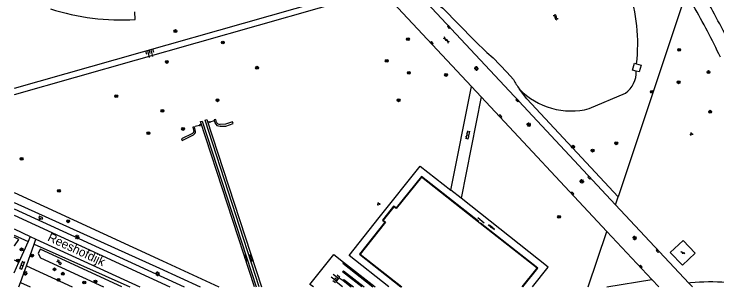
# Model space of a CAD drawing. Extents: x 128000 to 131008, y 398996 to 402500.
# Drawn here: x 128000 to 128199.6, y 399000 to 399077.6 of the extents above; entities that cross this region are included whole.
import ezdxf

# ---------------------------------------------------------------- set-up
doc = ezdxf.new("R2010")
doc.units = 0
for name, color, linetype in [('gg-afsc-hekwerk', 7, 'Continuous'), ('gg-afsc-muur', 7, 'Continuous'), ('gg-anno-openbare ruimte label', 7, 'Continuous'), ('gg-knt-BGT kruinlijn', 7, 'Continuous'), ('gg-knt-bovenkant onderkant talud', 7, 'Continuous'), ('gg-knt-verharding', 7, 'Continuous'), ('gg-knt-verharding nz', 7, 'Continuous'), ('gg-kntw-bovenkant insteek waterloop', 7, 'Continuous'), ('gg-kntw-greppel-droge sloot', 7, 'Continuous'), ('gg-kwrk-betonelement', 7, 'Continuous'), ('gt-grn-groengrens', 7, 'Continuous'), ('gt-symb-boom', 7, 'Continuous'), ('gt-symb-camera', 7, 'Continuous'), ('gt-symb-gesloten verharding', 7, 'Continuous'), ('gt-symb-groenvak', 7, 'Continuous'), ('gt-symb-klinker verharding', 7, 'Continuous'), ('gt-symb-kolk', 7, 'Continuous'), ('gt-symb-lichtmast', 7, 'Continuous'), ('gt-symb-speelvoorziening', 7, 'Continuous'), ('gt-symb-talud symbool', 7, 'Continuous'), ('gt-symb-tegel verharding', 7, 'Continuous'), ('gt-symb-watersymbool', 7, 'Continuous')]:
    doc.layers.add(name, color=color, linetype=linetype)

# ---------------------------------------------------------------- blocks, each defined once
blk = doc.blocks.new('gt0-KOLK')
at = {"layer": 'gt-symb-kolk'}
blk.add_lwpolyline([(0, 0), (0.38, 0), (0.38, 0.4), (-0.38, 0.4), (-0.38, 0), (0, 0)], dxfattribs=at)
blk = doc.blocks.new('gt0-WA')
at = {"layer": 'gt-symb-watersymbool'}
for centre, start, end in [((-0.32, 0.02), 28.0725, 151.9275), ((0.43, 0.42), 208.0725, 331.9275), ((-0.32, -0.43), 28.0725, 151.9275), ((0.43, -0.03), 208.0725, 331.9275)]:
    blk.add_arc(centre, 0.425, start, end, dxfattribs=at)
blk = doc.blocks.new('gt0-BOOM')
at = {"layer": 'gt-symb-boom'}
for radius in [0.4, 0.2]:
    blk.add_circle((0, 0), radius, dxfattribs=at)
blk = doc.blocks.new('gt0-TALUD_1')
at = {"layer": 'gt-symb-talud symbool'}
for p, q in [((-1, -1), (-1, 0)), ((-0.5, -2), (-0.5, 0)), ((0.5, -2), (0.5, 0)), ((1, -1), (1, 0)), ((0, -1), (0, 0))]:
    blk.add_line(p, q, dxfattribs=at)
blk = doc.blocks.new('gt0-GRVAK')
at = {"layer": 'gt-symb-groenvak'}
for p, q in [((-0.11, 0.19), (-0.23, 0.24)), ((-0.18, 0.15), (0.09, 0.15)), ((-0.09, 0.21), (-0.16, 0.32)), ((-0.05, 0.21), (-0.05, 0.39)), ((0, 0.21), (0.06, 0.32)), ((0.01, 0.19), (0.13, 0.24)), ((0.26, -0.05), (0.2, 0.06)), ((0.3, -0.05), (0.3, 0.13)), ((0.35, -0.05), (0.41, 0.06)), ((-0.25, -0.23), (-0.36, -0.18)), ((-0.32, -0.26), (-0.05, -0.26)), ((-0.23, -0.21), (-0.29, -0.1)), ((-0.18, -0.2), (-0.18, -0.02)), ((-0.14, -0.21), (-0.07, -0.1)), ((-0.12, -0.23), (0, -0.18)), ((0.24, -0.07), (0.12, -0.02)), ((0.17, -0.11), (0.44, -0.11)), ((0.37, -0.07), (0.49, -0.02))]:
    blk.add_line(p, q, dxfattribs=at)
blk = doc.blocks.new('gt0-GESVH1')
at = {"layer": 'gt-symb-gesloten verharding'}
for p, q in [((-0.99, -0.26), (0.01, 0.24)), ((0.01, -0.26), (-0.99, 0.24)), ((0.01, 0.24), (1.01, -0.26)), ((1.01, 0.24), (0.01, -0.26))]:
    blk.add_line(p, q, dxfattribs=at)
blk = doc.blocks.new('gt0-LMAST')
at = {"layer": 'gt-symb-lichtmast'}
for p, q in [((-0.18, 0.17), (-0.45, 0.44)), ((-0.01, 0.25), (-0.01, 0.62)), ((0.17, 0.17), (0.44, 0.44)), ((-0.26, 0), (-0.63, 0)), ((-0.18, -0.18), (-0.45, -0.45)), ((-0.01, -0.25), (-0.01, -0.63)), ((0.44, -0.45), (0.17, -0.18)), ((0.24, 0), (0.62, 0))]:
    blk.add_line(p, q, dxfattribs=at)
blk.add_circle((-0.01, 0), 0.25, dxfattribs=at)
blk = doc.blocks.new('gt0-KL1')
at = {"layer": 'gt-symb-klinker verharding'}
for p, q in [((-1.15, 0.3), (1.15, 0.3)), ((-1, -0.3), (-1, 0.3)), ((-0.5, 0.3), (-0.5, 0.45)), ((0, -0.3), (0, 0.3)), ((0.5, 0.3), (0.5, 0.45)), ((1, -0.3), (1, 0.3)), ((-1.15, -0.3), (1.15, -0.3)), ((-0.5, -0.45), (-0.5, -0.3)), ((0.5, -0.45), (0.5, -0.3))]:
    blk.add_line(p, q, dxfattribs=at)
blk = doc.blocks.new('gt0-CAMERA')
at = {"layer": 'gt-symb-camera'}
for points in [[(0.07, 0.48), (0.75, 0.16), (0.92, 0.51), (-0.12, 1), (-0.28, 0.65), (-0.07, 0.55)], [(0.07, 0.48), (0.07, 0), (-0.07, 0), (-0.07, 0.55)]]:
    blk.add_lwpolyline(points, dxfattribs=at)
blk = doc.blocks.new('gt0-SV')
at = {"layer": 'gt-symb-speelvoorziening'}
for p, q in [((-0.48, 0.26), (-0.08, 0.1)), ((0.54, -0.08), (-0.45, 0.32)), ((0.13, 0.01), (0.51, -0.14))]:
    blk.add_line(p, q, dxfattribs=at)
for centre, radius, start, end in [((-0.47, 0.29), 0.0369, 63.6251, 252.6602), ((0, -0.01), 0.128, 127.6866, 8.5986), ((0.53, -0.11), 0.0363, 243.5085, 72.5436)]:
    blk.add_arc(centre, radius, start, end, dxfattribs=at)
blk = doc.blocks.new('gt0-TEG1')
at = {"layer": 'gt-symb-tegel verharding'}
for p, q in [((-1.13, 0), (1.12, 0)), ((-0.9, -0.25), (-0.9, 0.25)), ((-0.45, -0.25), (-0.45, 0.25)), ((0, -0.25), (0, 0.25)), ((0.45, -0.25), (0.45, 0.25)), ((0.9, -0.25), (0.9, 0.25))]:
    blk.add_line(p, q, dxfattribs=at)

msp = doc.modelspace()

# ---------------------------------------------------------------- linework, layer by layer
at = {"layer": 'gg-afsc-hekwerk'}
for p, q in [((128052.69, 399045.93), (128051.41, 399045.6)), ((128056.86, 399047.27), (128055.62, 399046.86)), ((128133.55, 399018.17), (128131.69, 399019.64)), ((128098.12, 399009.3), (128109.88, 399000))]:
    msp.add_line(p, q, dxfattribs=at)
for points in [[(128131.96, 399018.59), (128115.72, 399031.43), (128108.51, 399022.49), (128107.81, 399023.01), (128104.61, 399018.97), (128105.32, 399018.41), (128098.12, 399009.3)], [(128144.54, 399000), (128148.77, 399005.33), (128132.48, 399018.17)]]:
    msp.add_lwpolyline(points, dxfattribs=at)
at = {"layer": 'gg-afsc-muur'}
msp.add_line((128052.69, 399045.93), (128052.7, 399045.86), dxfattribs=at)
for points in [[(128052.7, 399045.86), (128052.94, 399045.93), (128052.87, 399046.2), (128052.63, 399046.13), (128052.69, 399045.93)], [(128055.32, 399046.96), (128055.56, 399047.03), (128055.62, 399046.86)], [(128055.62, 399046.86), (128055.64, 399046.77), (128055.4, 399046.7), (128055.32, 399046.96)]]:
    msp.add_lwpolyline(points, dxfattribs=at)
at = {"layer": 'gg-knt-BGT kruinlijn'}
msp.add_lwpolyline([(128078.95, 399109.26), (128101.38, 399085.3), (128000, 399056.41)], dxfattribs=at)
at = {"layer": 'gg-knt-bovenkant onderkant talud'}
for points in [[(128079.75, 399110.39), (128104.01, 399084.31), (128000, 399054.57)], [(128085.06, 399000), (128084.03, 399000.71), (128090.83, 399009.27), (128093.61, 399007.09)], [(128093.25, 399000), (128091.49, 399001.41), (128092.38, 399002.62), (128093.47, 399001.8)]]:
    msp.add_lwpolyline(points, dxfattribs=at)
at = {"layer": 'gg-knt-verharding'}
for p, q in [((128007.41, 399188.33), (128129.97, 399056.96)), ((128124.09, 399027.49), (128129.97, 399056.96)), ((128129.97, 399056.96), (128132.7, 399054.04)), ((128132.7, 399054.04), (128126.99, 399025.2)), ((128132.7, 399054.04), (128168.35, 399015.81)), ((128126.99, 399025.2), (128124.09, 399027.49)), ((128000, 399022.24), (128048.27, 399000)), ((128191.69, 399001.04), (128170.85, 399023.39)), ((128000, 399016.49), (128004.6, 399014.36)), ((128004.6, 399014.36), (128003.98, 399012.95)), ((128004.6, 399014.36), (128006.2, 399013.62)), ((128168.35, 399015.81), (128181.16, 399002.09)), ((128003.98, 399012.95), (128001.35, 399007.05)), ((128003.51, 399006.05), (128005.69, 399012.18)), ((128005.69, 399012.18), (128006.2, 399013.62)), ((128006.2, 399013.62), (128035.69, 399000)), ((128000, 399003.99), (128001.35, 399007.05)), ((128001.81, 399001.28), (128003.51, 399006.05)), ((128093.61, 399007.09), (128102.58, 399000)), ((128168.4, 399000), (128181.16, 399002.09)), ((128181.16, 399002.09), (128183.1, 399000)), ((128001.35, 399000), (128001.81, 399001.28)), ((128001.81, 399001.28), (128004.58, 399000)), ((128093.47, 399001.8), (128095.74, 399000)), ((128191.69, 399001.04), (128192.66, 399000))]:
    msp.add_line(p, q, dxfattribs=at)
for points in [[(128170.85, 399023.39), (128142.05, 399054.28), (128080.14, 399120.59)], [(128068.25, 399000), (128052.95, 399047.03), (128053.39, 399047.17), (128068.77, 399000)], [(128069.64, 399000), (128054.31, 399047.43), (128054.76, 399047.58), (128070.26, 399000)], [(128106.49, 399000), (128095.17, 399008.96), (128103.67, 399019.71), (128115.39, 399034.37), (128124.09, 399027.49)], [(128144.35, 399000), (128148.56, 399005.3), (128132.39, 399018.05), (128115.74, 399031.22), (128108.53, 399022.28), (128107.84, 399022.8), (128104.82, 399018.99), (128105.53, 399018.43), (128098.33, 399009.33), (128110.12, 399000)], [(128147.23, 399000), (128151.72, 399005.67), (128126.99, 399025.2)], [(128189.82, 399006.15), (128193.46, 399009.58), (128190.02, 399013.22), (128186.38, 399009.8), (128189.82, 399006.15)], [(128093.61, 399007.09), (128093.36, 399006.78), (128101.93, 399000)], [(128098.76, 399000), (128093.33, 399004.3), (128093.58, 399004.61), (128099.41, 399000)], [(128093.47, 399001.8), (128093.71, 399002.12), (128096.38, 399000)]]:
    msp.add_lwpolyline(points, dxfattribs=at)
for centre, radius, start, end in [((128007.68, 398974.12), 217.44, 25.4027, 29.7543), ((127991.92, 398965.34), 231.42, 25.5931, 29.6798)]:
    msp.add_arc(centre, radius, start, end, dxfattribs=at)
at = {"layer": 'gg-knt-verharding nz'}
msp.add_line((128000, 399020.4), (128044.27, 399000), dxfattribs=at)
at = {"layer": 'gg-kntw-bovenkant insteek waterloop'}
msp.add_line((128163.36, 399050.69), (128173.64, 399055.07), dxfattribs=at)
for points in [[(128081.22, 399126.21), (128081.55, 399125.38), (128082.38, 399120.6), (128084.89, 399118.4), (128085.76, 399116.26), (128088.47, 399112.9), (128090.5, 399112.72), (128097.76, 399105.12), (128101.76, 399099.2), (128118.49, 399081.76), (128121.81, 399079.22), (128130.8, 399070.07), (128134.26, 399066.61), (128136.07, 399065.1), (128140, 399061.02), (128141.86, 399058.95)], [(128000, 399011.78), (128000.16, 399011.7), (128001.35, 399013.5), (128000, 399014.12)], [(128030.57, 399000), (128007.38, 399010.71), (128006.81, 399009.55), (128007.49, 399008.3), (128025.38, 399000)]]:
    msp.add_lwpolyline(points, dxfattribs=at)
for centre, radius, start, end in [((128128.35, 399069.17), 48.78, 353.2544, 18.6031), ((128169.26, 399061.11), 7.46, 305.9387, 1.9118), ((128159.91, 399068.27), 20.32, 207.3168, 216.2447), ((128158.21, 399070.47), 20.44, 224.0612, 284.6125)]:
    msp.add_arc(centre, radius, start, end, dxfattribs=at)
at = {"layer": 'gg-kntw-greppel-droge sloot'}
for points in [[(128000, 399026.87), (128042.17, 399007.39), (128058.14, 399000)], [(128000, 399024.03), (128041.31, 399005.3), (128052.82, 399000)]]:
    msp.add_lwpolyline(points, dxfattribs=at)
at = {"layer": 'gg-kwrk-betonelement'}
for points in [[(128176.72, 399061.36), (128175.63, 399061.67), (128176.18, 399063.61), (128176.79, 399063.44)], [(128176.79, 399063.44), (128178.09, 399063.07), (128177.54, 399061.13), (128176.72, 399061.36)]]:
    msp.add_lwpolyline(points, dxfattribs=at)
at = {"layer": 'gt-grn-groengrens'}
for p, q in [((128189.95, 399080.77), (128171.58, 399025.59)), ((128034.41, 399076.06), (128034.32, 399078.17)), ((128145.61, 399053.49), (128143.52, 399056.26)), ((128171.58, 399025.59), (128145.61, 399053.49)), ((128170.85, 399023.39), (128171.58, 399025.59)), ((128000, 399014.73), (128003.98, 399012.95)), ((128163.08, 399000), (128168.35, 399015.81)), ((128005.69, 399012.18), (128032.9, 399000)), ((128000, 399007.67), (128001.35, 399007.05)), ((128003.51, 399006.05), (128016.54, 399000)), ((128192.13, 399001.16), (128191.69, 399001.04))]:
    msp.add_line(p, q, dxfattribs=at)
for points in [[(128057.53, 399046.8), (128057.34, 399047.64), (128056.86, 399047.53), (128057.05, 399046.64)], [(128058.51, 399045.71), (128060.16, 399045.75), (128062.19, 399046.5), (128062.02, 399046.97), (128060.06, 399046.25), (128058.49, 399046.21)], [(128051.58, 399044.24), (128051.27, 399045.52), (128050.78, 399045.4), (128051.07, 399044.22)], [(128050.7, 399043.65), (128047.55, 399042.08), (128047.77, 399041.63), (128050.94, 399043.21)]]:
    msp.add_lwpolyline(points, dxfattribs=at)
for centre, radius, start, end in [((128030.19, 399140.01), 64.09, 251.9734, 273.7748), ((128058.45, 399047.23), 1.52, 202.892, 272.4597), ((128058.45, 399047.23), 1.02, 205.1524, 272.4502), ((128050.2, 399044.38), 0.885, 304.562, 349.147), ((128050.17, 399044.4), 1.42, 302.9147, 353.2356), ((128198.27, 398930.28), 71.14, 78.5283, 94.9488)]:
    msp.add_arc(centre, radius, start, end, dxfattribs=at)

# ---------------------------------------------------------------- block references
at = {"layer": 'gt-symb-boom'}
for p in [(128045.82, 399072.75), (128059.3, 399069.51), (128111.88, 399070.42), (128188.89, 399067.4), (128043.39, 399063.97), (128105.84, 399064.28), (128069.01, 399062.32), (128112.1, 399060.89), (128122.69, 399060.26), (128197.26, 399061.09), (128188.75, 399058.18), (128181.14, 399055.49), (128029.04, 399054.24), (128057.76, 399053.07), (128109.22, 399053.07), (128042.13, 399050.08), (128197.71, 399049.82), (128038.14, 399043.73), (128047.99, 399044.92), (128158.77, 399039.87), (128171.04, 399040.84), (128164.32, 399038.76), (128002.14, 399036.42), (128012.75, 399027.35), (128154.79, 399019.93), (128015.36, 399018.67), (128002.15, 399010.69), (128001.1, 399007.49), (128005.1, 399008.91), (128011.48, 399005.01), (128013.86, 399003.76), (128012.6, 399002.01), (128023.09, 399001.56), (128019.94, 399001.29)]:
    msp.add_blockref('gt0-BOOM', p, dxfattribs=at)
at = {"layer": 'gt-symb-camera'}
msp.add_blockref('gt0-CAMERA', (128007.28, 399019.12), dxfattribs=at)
at = {"layer": 'gt-symb-gesloten verharding'}
for p, rotation in [((128122.78, 399070.23), -45.000000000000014), ((128065.81, 399008.23), -71.58316555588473), ((128067.26, 399008.23), -71.583165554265)]:
    msp.add_blockref('gt0-GESVH1', p, dxfattribs=dict(at, rotation=rotation))
at = {"layer": 'gt-symb-groenvak'}
for p in [(128192.38, 399043.51), (128103.53, 399023.64)]:
    msp.add_blockref('gt0-GRVAK', p, dxfattribs=at)
at = {"layer": 'gt-symb-klinker verharding'}
for p, rotation in [((128128.8, 399043.19), -101.88275886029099), ((128002.26, 399006.13), -109.99289398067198)]:
    msp.add_blockref('gt0-KL1', p, dxfattribs=dict(at, rotation=rotation))
at = {"layer": 'gt-symb-kolk'}
for p, rotation in [((128123.62, 399074.02), 133.01389341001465), ((128118.52, 399069.24), -46.6620438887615), ((128143.07, 399053.19), 133.09489797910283), ((128137.99, 399048.39), -46.6620438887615), ((128163.54, 399031.24), 133.01389341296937), ((128158.45, 399026.44), -46.66204389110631), ((128182.97, 399010.39), 133.01389341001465), ((128177.89, 399005.6), -47.02517386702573)]:
    msp.add_blockref('gt0-KOLK', p, dxfattribs=dict(at, rotation=rotation))
at = {"layer": 'gt-symb-lichtmast'}
for p in [(128131.32, 399062.1), (128146.2, 399046.15), (128161.27, 399030.01), (128017.94, 399014.17), (128176.27, 399013.93), (128003.18, 399003.93), (128040.77, 399003.74)]:
    msp.add_blockref('gt0-LMAST', p, dxfattribs=at)
at = {"layer": 'gt-symb-speelvoorziening'}
msp.add_blockref('gt0-SV', (128189.91, 399009.69), dxfattribs=at)
at = {"layer": 'gt-symb-talud symbool'}
for p, xscale, yscale, rotation in [((128038.43, 399067.32), 1.000259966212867, 1.000259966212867, 15.898187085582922), ((128091.94, 399002.02), 1.0000499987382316, 1.0000499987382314, -127.44283634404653)]:
    msp.add_blockref('gt0-TALUD_1', p, dxfattribs=dict(at, xscale=xscale, yscale=yscale, rotation=rotation))
at = {"layer": 'gt-symb-tegel verharding', "rotation": -37.89006281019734}
msp.add_blockref('gt0-TEG1', (128135.6, 399017.05), dxfattribs=at)
at = {"layer": 'gt-symb-watersymbool'}
for p, rotation in [((128153.79, 399076.73), -47.148091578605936), ((128012.88, 399006.97), 155.22886109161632)]:
    msp.add_blockref('gt0-WA', p, dxfattribs=dict(at, rotation=rotation))

# ---------------------------------------------------------------- texts
at = {"layer": 'gg-anno-openbare ruimte label'}
msp.add_text('Reeshofdijk', height=2.5, rotation=335, dxfattribs=at).set_placement((128009.31, 399013.24))

doc.saveas('drawing.dxf')
